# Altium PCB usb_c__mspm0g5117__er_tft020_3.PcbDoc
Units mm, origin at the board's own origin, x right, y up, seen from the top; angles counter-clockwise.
Board outline 82 x 52 mm, 2 copper layers (Top, Bottom), stack 0 mm thick; 29 components, 27 nets, 174 pads, 100 vias.
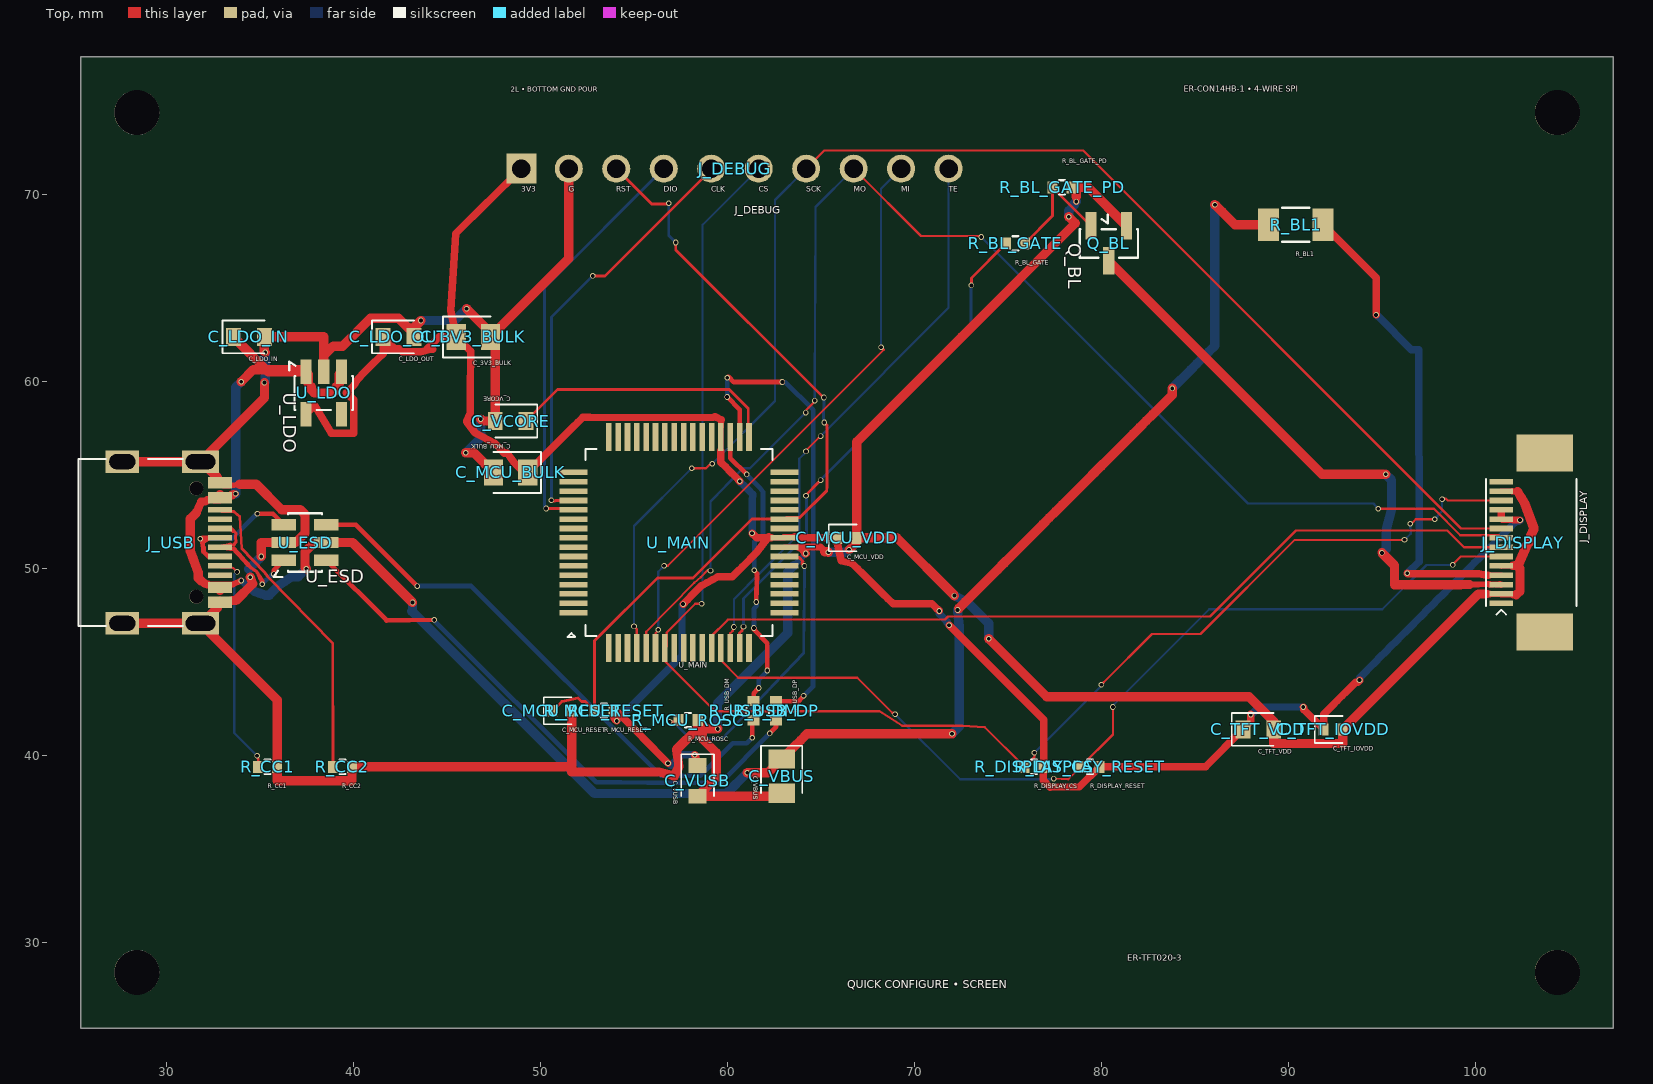
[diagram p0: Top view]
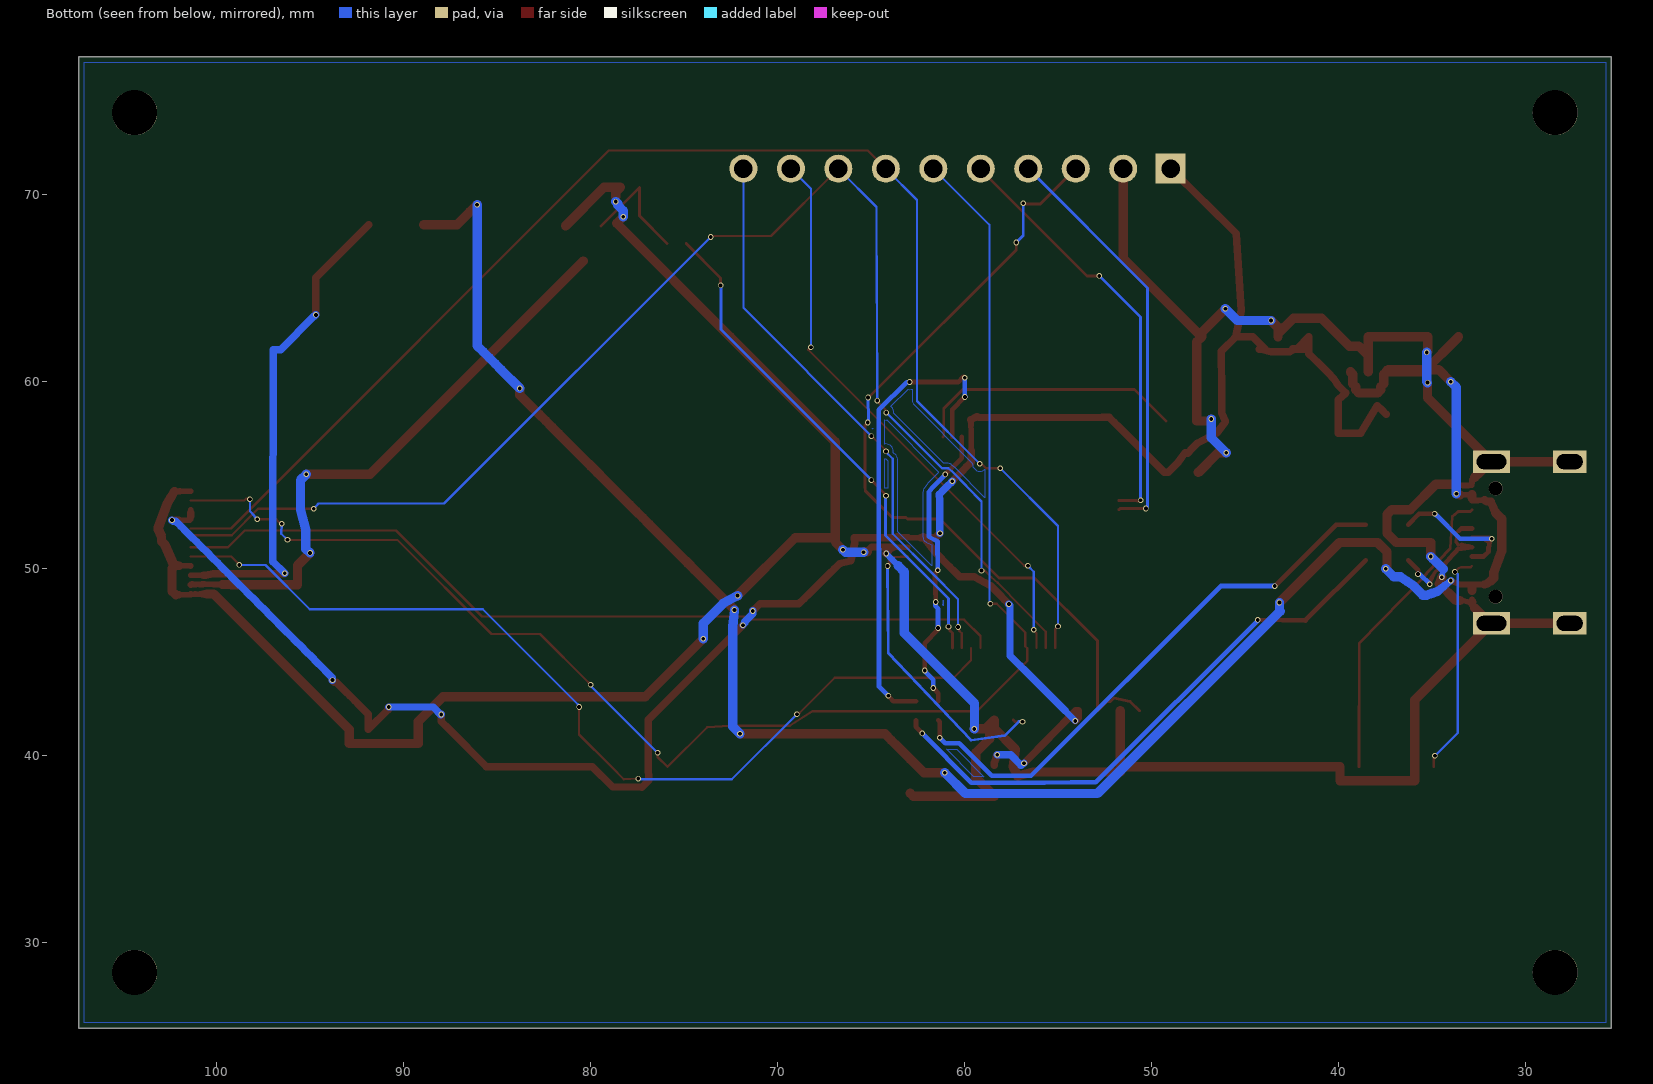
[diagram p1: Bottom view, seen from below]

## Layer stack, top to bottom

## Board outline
25.4,77.4 107.4,77.4 107.4,25.4 25.4,25.4

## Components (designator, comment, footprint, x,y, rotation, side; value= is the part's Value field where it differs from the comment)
C_3V3_BULK "" TSCIRCUIT-2.8500x1.4000mm 46.4,62.4 r0 top
C_LDO_IN "" TSCIRCUIT-2.4500x0.9500mm 34.4,62.4 r0 top
C_LDO_OUT "" TSCIRCUIT-2.4500x0.9500mm 42.4,62.4 r0 top
C_MCU_BULK "" TSCIRCUIT-2.8500x1.4000mm 48.4,55.15 r180 top
C_MCU_RESET "" TSCIRCUIT-1.5600x0.6400mm 51.15,42.4 r0 top
C_MCU_VDD "" TSCIRCUIT-1.5600x0.6400mm 66.4,51.65 r0 top
C_TFT_IOVDD "" TSCIRCUIT-1.5600x0.6400mm 92.4,41.4 r0 top
C_TFT_VDD "" TSCIRCUIT-2.4500x0.9500mm 88.4,41.4 r0 top
C_VBUS "" TSCIRCUIT-1.4000x2.8500mm 62.9,38.9 r270 top
C_VCORE "" TSCIRCUIT-2.4500x0.9500mm 48.4,57.9 r180 top
C_VUSB "" TSCIRCUIT-0.9500x2.4500mm 58.4,38.65 r270 top
J_DEBUG "" TSCIRCUIT-24.3600x1.5000mm 60.4,71.4 r0 top
J_DISPLAY "" TSCIRCUIT-4.4500x11.5800mm 103,51.4 r90 top
J_USB "" TSCIRCUIT-6.7732x9.8502mm 30.113,51.4 r90 top
Q_BL "" TSCIRCUIT-2.5000x3.3500mm 80.4,67.4 r270 top
R_BL1 "" TSCIRCUIT-4.0500x1.7500mm 90.4,68.4 r0 top
R_BL_GATE "" TSCIRCUIT-1.5600x0.6400mm 75.4,67.4 r0 top
R_BL_GATE_PD "" TSCIRCUIT-1.5600x0.6400mm 77.9,70.4 r0 top
R_CC1 "" TSCIRCUIT-1.5600x0.6400mm 35.4,39.4 r0 top
R_CC2 "" TSCIRCUIT-1.5600x0.6400mm 39.4,39.4 r0 top
R_DISPLAY_CS "" TSCIRCUIT-1.5600x0.6400mm 76.4,39.4 r0 top
R_DISPLAY_RESET "" TSCIRCUIT-1.5600x0.6400mm 79.4,39.4 r0 top
R_MCU_RESET "" TSCIRCUIT-1.5600x0.6400mm 53.4,42.4 r0 top
R_MCU_ROSC "" TSCIRCUIT-1.5600x0.6400mm 57.9,41.9 r0 top
R_USB_DM "" TSCIRCUIT-0.6400x1.5600mm 61.4,42.4 r90 top
R_USB_DP "" TSCIRCUIT-0.6400x1.5600mm 62.6,42.4 r90 top
U_ESD "" TSCIRCUIT-3.6000x2.5000mm 37.4,51.4 r0 top
U_LDO "" TSCIRCUIT-2.5000x3.6000mm 38.4,59.4 r270 top
U_MAIN "" TSCIRCUIT-12.8000x12.8000mm 57.4,51.4 r0 top

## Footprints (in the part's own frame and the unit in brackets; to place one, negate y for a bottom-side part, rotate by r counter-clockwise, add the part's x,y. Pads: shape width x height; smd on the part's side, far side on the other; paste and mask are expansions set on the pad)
TSCIRCUIT-0.6400x1.5600mm [mm]
  rect 0.54x0.64 smd: 1(-0.51,0) 2(0.51,0)
  silkscreen extent -0.15,-0.38 0.15,0.38
TSCIRCUIT-0.9500x2.4500mm [mm]
  rect 0.8x0.95 smd: 1(-0.825,0) 2(0.825,0)
  silkscreen extent -1.43,-0.87 0.82,0.87
TSCIRCUIT-1.4000x2.8500mm [mm]
  rect 1.025x1.4 smd: 1(-0.913,0) 2(0.913,0)
  silkscreen extent -1.62,-1.1 0.91,1.1
TSCIRCUIT-1.5600x0.6400mm [mm]
  rect 0.54x0.64 smd: 1(-0.51,0) 2(0.51,0)
  silkscreen extent -0.98,-0.72 0.51,0.72
TSCIRCUIT-2.4500x0.9500mm [mm]
  rect 0.8x0.95 smd: 1(-0.825,0) 2(0.825,0)
  silkscreen extent -1.43,-0.87 0.82,0.87
TSCIRCUIT-2.5000x3.3500mm [mm]
  rect 1.475x0.6 smd: 1(-0.938,-0.95) 2(-0.938,0.95) 3(0.937,0)
  silkscreen extent -1.54,-1.56 0.76,1.56
TSCIRCUIT-2.5000x3.6000mm [mm]
  rect 1.325x0.6 smd: 1(-1.137,-0.95) 2(-1.137,0) 3(-1.137,0.95) 4(1.138,0.95) 5(1.138,-0.95)
  silkscreen extent -1.69,-1.84 0.91,1.56
TSCIRCUIT-2.8500x1.4000mm [mm]
  rect 1.025x1.4 smd: 1(-0.913,0) 2(0.913,0)
  silkscreen extent -1.63,-1.1 0.91,1.1
TSCIRCUIT-3.6000x2.5000mm [mm]
  rect 1.325x0.6 smd: 1(-1.137,-0.95) 2(-1.137,0) 3(-1.137,0.95) 4(1.138,0.95) 5(1.138,0) 6(1.138,-0.95)
  silkscreen extent -1.69,-1.84 0.91,1.56
TSCIRCUIT-4.0500x1.7500mm [mm]
  rect 1.125x1.75 smd: 1(-1.462,0) 2(1.463,0)
  silkscreen extent -0.73,-0.91 0.73,0.91
TSCIRCUIT-4.4500x11.5800mm [mm]
  rect 0.3x1.25 smd: 1(-3.25,1.6) 2(-2.75,1.6) 3(-2.25,1.6) 4(-1.75,1.6) 5(-1.25,1.6) 6(-0.75,1.6) 7(-0.25,1.6) 8(0.25,1.6) 9(0.75,1.6) 10(1.25,1.6) 11(1.75,1.6) 12(2.25,1.6) 13(2.75,1.6) 14(3.25,1.6)
  rect 2x3 smd: 15(4.79,-0.725) 16(-4.79,-0.725)
  silkscreen extent -3.85,-2.43 3.4,2.42
TSCIRCUIT-6.7732x9.8502mm [mm]
  rect 0.3x1.3 smd: 1(-3.35,-2.737) 2(-3.05,-2.737) 3(-2.55,-2.737) 4(-2.25,-2.737) 5(-1.75,-2.737) 6(-1.25,-2.737) 7(-0.75,-2.737) 8(-0.25,-2.737) 9(0.25,-2.737) 10(0.75,-2.737) 11(1.25,-2.737) 12(1.75,-2.737) 13(2.55,-2.737) 14(2.25,-2.737) 15(3.35,-2.737) 16(3.05,-2.737)
  rect 1.2x2 hole 0.8 slot 1.6 at 90 deg: 17(-4.325,-1.693) 18(4.325,-1.693)
  rect 1.2x1.8 hole 0.8 slot 1.4 at 90 deg: 19(4.325,2.487) 20(-4.325,2.487)
  round 0.75 hole 0.75 unplated: NPTH-1(-2.9,-1.468) NPTH-2(2.9,-1.468)
  silkscreen extent -4.47,-0.75 4.47,4.83
TSCIRCUIT-12.8000x12.8000mm [mm]
  rect 1.5x0.3 smd: 1(-5.65,-3.75) 2(-5.65,-3.25) 3(-5.65,-2.75) 4(-5.65,-2.25) 5(-5.65,-1.75) 6(-5.65,-1.25) 7(-5.65,-0.75) 8(-5.65,-0.25) 9(-5.65,0.25) 10(-5.65,0.75) 11(-5.65,1.25) 12(-5.65,1.75) 13(-5.65,2.25) 14(-5.65,2.75) 15(-5.65,3.25) 16(-5.65,3.75) 33(5.65,3.75) 34(5.65,3.25) 35(5.65,2.75) 36(5.65,2.25) 37(5.65,1.75) 38(5.65,1.25) 39(5.65,0.75) 40(5.65,0.25) 41(5.65,-0.25) 42(5.65,-0.75) 43(5.65,-1.25) 44(5.65,-1.75) 45(5.65,-2.25) 46(5.65,-2.75) 47(5.65,-3.25) 48(5.65,-3.75)
  rect 0.3x1.5 smd: 17(-3.75,5.65) 18(-3.25,5.65) 19(-2.75,5.65) 20(-2.25,5.65) 21(-1.75,5.65) 22(-1.25,5.65) 23(-0.75,5.65) 24(-0.25,5.65) 25(0.25,5.65) 26(0.75,5.65) 27(1.25,5.65) 28(1.75,5.65) 29(2.25,5.65) 30(2.75,5.65) 31(3.25,5.65) 32(3.75,5.65) 49(3.75,-5.65) 50(3.25,-5.65) 51(2.75,-5.65) 52(2.25,-5.65) 53(1.75,-5.65) 54(1.25,-5.65) 55(0.75,-5.65) 56(0.25,-5.65) 57(-0.25,-5.65) 58(-0.75,-5.65) 59(-1.25,-5.65) 60(-1.75,-5.65) 61(-2.25,-5.65) 62(-2.75,-5.65) 63(-3.25,-5.65) 64(-3.75,-5.65)
  silkscreen extent -5.95,-5.05 5,5
TSCIRCUIT-24.3600x1.5000mm [mm]
  rect 1.6x1.6 hole 1: 1(-11.43,0)
  round 1.5 hole 1: 2(-8.89,0) 3(-6.35,0) 4(-3.81,0) 5(-1.27,0) 6(1.27,0) 7(3.81,0) 8(6.35,0) 9(8.89,0) 10(11.43,0)

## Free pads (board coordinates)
  round 2.4 hole 2.4 unplated: NPTH-3(28.4,28.4) NPTH-4(104.4,28.4) NPTH-5(28.4,74.4) NPTH-6(104.4,74.4)

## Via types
v1: diameter 0.3, hole 0.2, Top to Bottom, 100 vias

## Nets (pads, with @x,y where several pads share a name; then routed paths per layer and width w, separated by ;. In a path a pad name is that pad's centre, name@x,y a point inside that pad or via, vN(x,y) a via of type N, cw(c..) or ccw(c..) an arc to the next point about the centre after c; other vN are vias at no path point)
".J_DEBUG > .pin4 to .U_MAIN > .pin12": J_DEBUG.4 U_MAIN.12 | length 22.3
  Top w0.15: v1(50.297,53.22) 51.68,53.22 U_MAIN.12
  Bottom w0.15: v1(50.297,53.22) 50.285,53.232 50.204,53.313 50.204,53.447 50.204,65.014 J_DEBUG.4
".J_DEBUG > .pin5 to .U_MAIN > .pin13": J_DEBUG.5 U_MAIN.13 | length 22.9
  Top w0.15: v1(50.582,53.664) 50.63,53.616 50.764,53.616 50.799,53.65 U_MAIN.13 ; v1(52.787,65.664) 53.449,65.663 58.819,71.03 58.817,71.087 J_DEBUG.5
  Bottom w0.15: v1(50.582,53.664) 50.582,63.459 52.67,65.547 v1(52.787,65.664)
".U_MAIN > .pin42 to .R_MCU_ROSC > .pin1": R_MCU_ROSC.1 U_MAIN.42 | length 16.1
  Top w0.15: v1(56.896,41.815) 57.305,41.815 R_MCU_ROSC.1 ; U_MAIN.42 63.812,50.612 64.037,50.387 63.977,50.282 v1(64.117,50.142)
  Bottom w0.15: v1(56.896,41.815) 56.915,41.834 57.086,41.834 57.837,41.082 59.65,40.825 64.079,45.487 v1(64.117,50.142)
BACKLIGHT_ANODE_1: J_DISPLAY.4 R_BL1.2 | length 26.3
  Top w0.3: 100.775,49.65 100.8,49.65 100.9,49.65 101,49.65 101.1,49.65 101.2,49.65 101.3,49.65 J_DISPLAY.4
  Top w0.343: 100.7,49.65 100.775,49.65
  Top w0.4: R_BL1.2 94.701,65.562 v1(94.701,63.576) ; v1(96.371,49.758) 96.395,49.732 96.438,49.719 100.188,49.726 100.6,49.65 100.7,49.65
  Bottom w0.4: v1(94.701,63.576) 94.783,63.494 94.804,63.494 96.585,61.714 96.984,61.714 96.998,50.367 v1(96.371,49.758)
BACKLIGHT_CATHODE: J_DISPLAY.3 Q_BL.3 | length 31.7
  Top w0.303: J_DISPLAY.3@100.932,49.158 101.026,49.158 J_DISPLAY.3@101.12,49.159
  Top w0.309: J_DISPLAY.3@101.12,49.159 J_DISPLAY.3@101.214,49.16
  Top w0.311: J_DISPLAY.3@100.839,49.159 J_DISPLAY.3@100.932,49.158 ; J_DISPLAY.3@101.214,49.16 J_DISPLAY.3@101.307,49.163
  Top w0.325: 99.697,49.15 100.174,49.161 100.651,49.171 100.745,49.157
  Top w0.33: J_DISPLAY.3@100.776,49.157 J_DISPLAY.3@100.839,49.159
  Top w0.35: 100.745,49.157 100.775,49.157
  Top w0.352: J_DISPLAY.3@101.307,49.163 J_DISPLAY.3
  Top w0.5: Q_BL.3 87.313,59.549 91.807,55.055 v1(95.21,55.055) ; v1(95.012,50.843) 95.684,50.171 95.684,49.807 95.684,49.14 99.22,49.14 99.697,49.15
  Bottom w0.5: v1(95.012,50.843) 95.234,51.053 95.234,51.547 95.235,52.041 95.525,53.15 95.525,54.74 v1(95.21,55.055)
BACKLIGHT_GATE: Q_BL.1 R_BL_GATE.2 R_BL_GATE_PD.1 | length 6.5
  Top w0.15: R_BL_GATE.2 77.39,68.88 R_BL_GATE_PD.1 79.45,68.34 Q_BL.1
BACKLIGHT_PWM: R_BL_GATE.1 U_MAIN.50 | length 27.6
  Top w0.15: U_MAIN.50 60.65,46.552 60.79,46.692 60.79,46.839 v1(60.859,46.903) ; v1(64.199,53.908) 64.231,53.978 64.886,54.633 64.886,54.65 v1(64.98,54.738) ; v1(73.049,65.154) 73.049,65.559 R_BL_GATE.1
  Bottom w0.15: v1(60.859,46.903) 60.854,48.403 63.16,50.709 64.227,51.776 64.227,53.763 64.227,53.904 v1(64.199,53.908) ; v1(64.98,54.738) 73.036,62.8 73.036,65.141 v1(73.049,65.154)
DISPLAY_CS_N: J_DEBUG.6 J_DISPLAY.12 R_DISPLAY_CS.1 U_MAIN.58 | length 82.5
  Top w0.12: v1(58.613,48.124) 58.281,48.124 56.749,46.592 56.749,45.849 U_MAIN.58 56.65,45.059 59.332,42.377 68.123,42.377 69.337,41.599 69.696,41.599 72.57,41.591 73.767,41.523 R_DISPLAY_CS.1 76.419,39.929 v1(76.419,40.146) ; v1(80.004,43.795) 80.13,43.921 80.133,43.921 82.713,46.501 85.31,46.501 90.35,51.541 v1(96.218,51.541) ; v1(96.53,52.405) 96.617,52.47 96.657,52.47 96.828,52.64 v1(97.835,52.64) ; v1(98.229,53.72) 98.255,53.746 98.44,53.746 98.536,53.65 J_DISPLAY.12
  Bottom w0.12: v1(58.613,48.124) 58.67,48.181 58.67,48.214 58.67,68.4 J_DEBUG.6 ; v1(76.419,40.146) 76.437,40.164 80.004,43.731 v1(80.004,43.795) ; v1(96.218,51.541) 96.224,51.547 96.552,51.875 v1(96.53,52.405) ; v1(97.835,52.64) 97.98,52.785 97.98,52.824 98.229,53.073 v1(98.229,53.72)
DISPLAY_DC: J_DISPLAY.7 U_MAIN.53 | length 45.6
  Top w0.12: U_MAIN.53 59.15,46.398 59.929,47.177 60.033,47.282 71.635,47.282 71.796,47.443 85.817,47.443 90.412,52.039 98.512,52.039 99.401,51.15 J_DISPLAY.7
DISPLAY_MISO: J_DEBUG.9 U_MAIN.59 | length 31.3
  Top w0.12: U_MAIN.59 56.15,46.541 56.298,46.689 56.298,46.736 v1(56.296,46.738) ; v1(56.608,50.153) 56.801,50.153 68.363,61.715 68.351,61.715 v1(68.216,61.85)
  Bottom w0.12: v1(56.296,46.738) 56.296,49.841 56.575,50.12 v1(56.608,50.153) ; v1(68.216,61.85) 68.216,70.326 J_DEBUG.9
DISPLAY_MOSI: J_DEBUG.8 J_DISPLAY.8 U_MAIN.60 | length 73.4
  Top w0.12: U_MAIN.60 55.65,46.629 58.217,49.242 58.564,49.543 58.918,49.897 v1(59.091,49.897) ; v1(64.181,58.352) 64.196,58.478 64.64,58.922 64.64,58.941 v1(64.672,58.994) ; J_DEBUG.8 70.352,67.798 73.508,67.798 73.53,67.798 v1(73.581,67.747) ; v1(94.815,53.201) 97.793,53.201 99.208,51.786 101.264,51.786 J_DISPLAY.8
  Bottom w0.12: v1(59.091,49.897) 59.091,53.594 60.654,55.195 60.867,55.37 61.208,55.37 v1@64.148,58.31 ; v1@64.148,58.31 v1(64.181,58.352) ; v1(64.672,58.994) 64.703,69.353 J_DEBUG.8 ; v1(73.581,67.747) 87.841,53.487 94.552,53.487 94.556,53.487 v1(94.815,53.201)
DISPLAY_RESET_N: J_DISPLAY.6 R_DISPLAY_RESET.1 U_MAIN.52 | length 50.9
  Top w0.12: U_MAIN.52 59.65,45.094 60.582,44.162 66.945,44.162 68.809,42.298 68.887,42.298 v1(68.968,42.217) ; v1(77.453,38.771) 78.225,38.735 R_DISPLAY_RESET.1 80.62,41.13 v1(80.62,42.602) ; v1(98.8,50.2) 98.818,50.218 98.818,50.244 99.225,50.65 J_DISPLAY.6
  Bottom w0.12: v1(68.968,42.217) 72.449,38.736 77.421,38.736 v1(77.453,38.771) ; v1(80.62,42.602) 80.692,42.7 80.692,42.743 85.779,47.831 95.032,47.831 97.402,50.2 v1(98.8,50.2)
DISPLAY_SCLK: J_DEBUG.7 J_DISPLAY.9 U_MAIN.61 | length 76
  Top w0.12: v1(55.001,46.91) 55.15,46.761 55.15,46.75 U_MAIN.61 ; v1(58.093,55.379) 58.848,55.379 59.02,55.551 59.113,55.551 v1(59.179,55.617) ; J_DEBUG.7 65.189,72.379 79.017,72.379 99.246,52.15 J_DISPLAY.9
  Bottom w0.12: v1(55.001,46.91) 55.001,52.287 58.091,55.377 v1(58.093,55.379) ; v1(59.179,55.617) 62.537,58.975 62.537,69.721 62.537,69.727 J_DEBUG.7
DISPLAY_TE: J_DEBUG.10 U_MAIN.51 | length 30.5
  Top w0.12: U_MAIN.51 60.15,46.55 60.291,46.691 60.291,46.821 v1(60.345,46.88) ; v1(64.201,56.272) 64.242,56.366 64.881,57.005 64.881,57.015 v1(64.982,57.092)
  Bottom w0.12: v1(60.345,46.88) 60.35,48.37 61.77,49.791 63.845,51.865 63.845,55.678 63.845,55.875 64.235,56.265 v1(64.201,56.272) ; v1(64.982,57.092) 71.83,63.964 J_DEBUG.10
GND: C_3V3_BULK.2 C_LDO_IN.2 C_LDO_OUT.2 C_MCU_BULK.2 C_MCU_RESET.2 C_MCU_VDD.2 C_TFT_IOVDD.2 C_TFT_VDD.2 C_VBUS.2 C_VCORE.2 C_VUSB.2 J_DEBUG.2 J_DISPLAY.2 J_DISPLAY.5 J_DISPLAY.13 J_USB.1 J_USB.2 J_USB.15 J_USB.16 J_USB.17 J_USB.18 J_USB.19 J_USB.20 Q_BL.2 R_BL_GATE_PD.2 R_CC1.2 R_CC2.2 R_MCU_ROSC.2 U_ESD.2 U_LDO.2 U_MAIN.41 | length 222.5
  Top w0.275: J_USB.1@32.849,48.2 J_USB.2
  Top w0.288: J_USB.15@32.849,54.6 J_USB.16 J_USB.16@32.945,54.461
  Top w0.3: J_USB.1@32.699,47.9 J_USB.1 J_USB.2@32.849,48.2 ; 32.699,54.9 J_USB.15 J_USB.16@32.849,54.6 ; J_USB.2 33,48.2 33.4,48.3 33.499,48.3 ; J_DISPLAY.2 101.4,48.6 101.8,48.6 J_DISPLAY.2@102.025,48.6 ; J_DISPLAY.5 J_DISPLAY.5@101.765,50.155 ; J_DISPLAY.13 101.702,54.15 J_DISPLAY.13@101.989,54.142 ; U_MAIN.41@63.144,51.15 U_MAIN.41 U_MAIN.41@63.144,51.15 ; U_MAIN.41@63.144,51.15 U_MAIN.41@63.238,51.15 ; U_MAIN.41@63.144,51.15 U_MAIN.41@63.238,51.15 ; U_MAIN.41@63.238,51.15 U_MAIN.41@63.331,51.15 ; U_MAIN.41@63.238,51.15 U_MAIN.41@63.331,51.15 ; U_MAIN.41@63.331,51.15 U_MAIN.41@63.425,51.15 ; U_MAIN.41@63.331,51.15 U_MAIN.41@63.425,51.15 ; U_MAIN.41@63.425,51.15 U_MAIN.41@63.519,51.15 ; U_MAIN.41@63.425,51.15 U_MAIN.41@63.519,51.15 ; U_MAIN.41@63.519,51.15 U_MAIN.41@63.612,51.15 ; U_MAIN.41@63.519,51.15 U_MAIN.41@63.612,51.15 ; U_MAIN.41@63.612,51.15 U_MAIN.41@63.706,51.15 ; U_MAIN.41@63.612,51.15 U_MAIN.41@63.706,51.15 ; U_MAIN.41@63.706,51.15 63.8,51.15 U_MAIN.41@63.706,51.15
  Top w0.301: J_DISPLAY.2@100.899,48.638 101.024,48.638 J_DISPLAY.2@101.149,48.639
  Top w0.308: J_DISPLAY.2@101.149,48.639 101.275,48.638 J_DISPLAY.2
  Top w0.312: J_USB.16@32.945,54.461 33.037,54.45 33.316,54.457 33.596,54.465 33.9,54.525
  Top w0.316: J_DISPLAY.5 101.801,50.155 J_DISPLAY.5@102.025,50.158
  Top w0.318: J_DISPLAY.5@101.765,50.155 102.129,50.16
  Top w0.324: 100.775,48.636 J_DISPLAY.2@100.899,48.638
  Top w0.334: J_DISPLAY.13@101.989,54.142 102.275,54.134
  Top w0.35: v1(78.658,69.64) 78.658,69.896 ; 100.774,48.636 100.775,48.636
  Top w0.375: U_MAIN.41@63.8,51.15 64.189,51.15 64.577,51.15 64.966,51.15 65.202,50.914 ; 100.648,48.637 100.774,48.636
  Top w0.4: U_MAIN.41@63.8,51.15 64.056,51.025 ; 102.025,48.6 102.2,48.6
  Top w0.433: 100.524,48.647 100.648,48.637
  Top w0.45: 64.056,51.025 64.17,50.83 v1(64.182,50.812)
  Top w0.475: v1(66.507,51.014) 66.91,51.417 C_MCU_VDD.2 ; 102.025,50.158 102.202,50.16 ; 102.129,50.16 102.2,50.2 102.4,50 102.4,49.6 ; 102.2,48.6 102.4,48.8 ; 102.275,54.134 102.456,53.826
  Top w0.5: J_USB.20 J_USB.17 ; J_USB.19 J_USB.18 ; J_USB.1@32.699,47.9 32.474,47.675 31.874,47.075 J_USB.17 ; 32.699,54.9 32.474,55.125 31.874,55.725 J_USB.18 ; 33.499,48.3 33.7,48.3 34.6,49.2 v1(34.469,49.537) ; 33.9,54.525 34.775,54.525 36.15,53.15 37.15,53.15 37.4,52.9 37.4,51.9 36.9,51.4 U_ESD.2 35.057,51.4 v1(35.057,50.65) ; v1(35.227,59.956) 35.227,59.146 J_USB.18 ; v1(35.268,61.571) 35.225,61.615 C_LDO_IN.2 38.4,62.4 U_LDO.2 38.4,61.4 38.9,61.9 39.4,61.9 40.9,63.4 42.4,63.4 43.225,62.575 C_LDO_OUT.2 43.225,62.9 43.578,63.253 v1(43.6,63.275) ; v1(46,56.2) 46.437,56.2 C_MCU_BULK.2 ; v1(46.042,63.91) 47.313,62.64 C_3V3_BULK.2 ; v1(46.805,58.005) 46.911,57.9 C_VCORE.2 47.575,62.138 C_3V3_BULK.2 ; J_DEBUG.2 51.51,66.597 C_3V3_BULK.2 ; v1(59.483,41.429) 59.182,41.429 58.881,41.429 58.646,41.664 R_MCU_ROSC.2 ; C_VBUS.2 62.737,37.825 C_VUSB.2 59.4,38.825 59.4,40.15 58.65,40.9 58.65,41.65 58.41,41.89 R_MCU_ROSC.2 ; 65.202,50.914 65.361,50.914 v1(65.399,50.876) ; v1(72.141,48.56) 69.051,51.65 C_MCU_VDD.2 66.91,52.137 66.91,52.623 66.91,53.11 66.91,53.596 66.91,54.083 66.91,54.569 66.91,55.056 66.91,55.543 66.91,56.782 72.529,62.401 78.605,68.476 v1(78.251,68.83) ; v1(73.977,46.249) 77.076,43.15 80.9,43.15 87.9,43.15 88.4,42.65 89.225,41.825 C_TFT_VDD.2 89.225,40.65 92.91,40.65 C_TFT_IOVDD.2 100.16,48.64 100.4,48.645 100.524,48.647 ; 78.658,69.896 78.658,70.152 R_BL_GATE_PD.2 79.287,70.4 Q_BL.2 ; 102.202,50.16 102.4,50.358 102.4,50.4 102.588,50.838 102.775,51.275 102.962,51.463 102.962,51.713 103.15,52.15 102.638,53.517 102.456,53.826 ; 102.4,48.8 102.4,49.2 102.4,49.6 ; J_USB.17 35.91,42.971 R_CC1.2 35.91,38.65 39.91,38.65 R_CC2.2 40.391,39.4 40.871,39.4 41.352,39.4 41.832,39.4 42.313,39.4 42.793,39.4 43.274,39.4 43.754,39.4 44.235,39.4 44.715,39.4 45.196,39.4 45.676,39.4 51.66,39.4 C_MCU_RESET.2 51.66,39.119 56.349,39.119 57.15,38.9 57.4,39.4 57.273,40.33 58.41,41.467 R_MCU_ROSC.2
  Bottom w0.3: 34.39,49.983 v1(34.469,49.537)
  Bottom w0.325: 63.547,50.158 63.864,50.485 v1(64.182,50.812)
  Bottom w0.5: 34.39,49.983 34.668,50.261 34.946,50.539 v1(35.057,50.65) ; v1(35.227,59.956) 35.268,59.997 v1(35.268,61.571) ; v1(43.6,63.275) 45.407,63.275 v1(46.042,63.91) ; v1(46,56.2) 46.805,57.005 v1(46.805,58.005) ; v1(59.483,41.429) 59.468,41.444 59.468,41.644 59.468,42.029 59.468,42.414 59.468,42.798 63.23,46.56 63.23,49.831 63.547,50.158 ; v1(65.399,50.876) 66.369,50.876 v1(66.507,51.014) ; v1(72.141,48.56) 72.9,48.15 73.977,47.073 v1(73.977,46.249) ; v1(78.251,68.83) 78.251,69.148 78.556,69.453 78.556,69.538 v1(78.658,69.64)
MAIN_RESET: C_MCU_RESET.1 J_DEBUG.3 R_MCU_RESET.1 U_MAIN.38 | length 44.8
  Top w0.15: C_MCU_RESET.1 51.137,42.897 52,43.075 52.184,42.897 52.393,42.897 R_MCU_RESET.1 52.89,46.145 56.252,49.507 58.161,49.507 59.816,51.162 61.304,52.65 U_MAIN.38 63.13,52.73 63.869,52.73 65.308,54.169 65.32,54.382 65.322,57.685 v1(65.173,57.82) ; J_DEBUG.3 55.948,69.502 56.764,69.502 56.816,69.502 v1(56.853,69.545) ; v1(57.233,67.451) 57.233,67.043 65.073,59.203 v1(65.16,59.157)
  Bottom w0.15: v1(56.853,69.545) 56.856,67.828 v1(57.233,67.451) ; v1(65.16,59.157) 65.129,57.971 65.179,57.921 65.179,57.826 v1(65.173,57.82)
MSP_VCORE: C_VCORE.1 U_MAIN.32 | length 14.5
  Top w0.15: C_VCORE.1 50.903,59.578 60.03,59.578 60.094,59.578 61.109,58.563 61.109,57.091 U_MAIN.32
usb-dm-mcu: R_USB_DM.2 U_MAIN.30 | length 15.9
  Top w0.25: U_MAIN.30 60.15,55.91 v1(61.026,55.042) ; R_USB_DM.2 61.4,43.335 61.63,43.565 61.63,43.573 v1(61.675,43.618) ; v1(61.414,46.828) 61.401,46.815 61.401,46.748 62.132,46.017 v1(62.132,44.553) ; v1(61.429,49.918) 61.433,49.914 61.433,49.902 61.579,49.756 v1(61.538,48.216)
  Bottom w0.25: v1(61.026,55.042) 61.077,54.983 61.733,54.327 61.9,54.1 61.9,51.7 61.443,51.47 v1(61.429,49.918) ; v1(61.414,46.828) 61.414,47.862 61.555,48.013 61.559,48.202 v1(61.538,48.216) ; v1(61.675,43.618) 61.675,44.063 62.067,44.455 62.067,44.488 v1(62.132,44.553)
usb-dm-phy: R_USB_DM.1 U_ESD.4 | length 30.2
  Top w0.25: U_ESD.4 40.122,52.35 43.244,49.228 ; 43.245,49.228 v1(43.403,49.07) ; v1(61.322,40.955) 61.322,41.812 R_USB_DM.1
  Bottom w0.25: v1(43.403,49.07) 46.283,49.07 56.443,38.917 58.538,38.917 60.281,40.653 61.029,40.653 61.31,40.934 61.31,40.943 v1(61.322,40.955)
usb-dm-port: J_USB.7 J_USB.9 U_ESD.3 | length 8.8
  Top w0.25: v1(31.799,51.6) 31.809,51.61 31.866,51.61 31.906,51.65 J_USB.9 32.275,51.65 31.9,51.4 31.963,51.131 31.963,50.925 31.962,50.9 32.238,50.65 32.442,50.65 32.645,50.65 J_USB.7 ; v1(34.85,52.94) 35.685,52.928 U_ESD.3
  Bottom w0.25: v1(31.799,51.6) 33.493,51.6 34.769,52.876 34.786,52.876 v1(34.85,52.94)
usb-dp-mcu: R_USB_DP.2 U_MAIN.31 | length 25.9
  Top w0.25: v1(59.977,59.187) 60.65,58.514 U_MAIN.31 ; v1(59.992,60.219) 60.029,60.256 60.056,60.256 60.327,59.985 v1(62.94,59.985) ; R_USB_DP.2 63.802,42.91 64.013,43.121 64.013,43.145 v1(64.072,43.204)
  Bottom w0.25: v1(59.977,59.187) 59.966,59.198 59.966,59.234 59.992,59.26 v1(59.992,60.219) ; v1(62.94,59.985) 62.954,59.971 63.095,59.971 64.593,58.503 64.579,43.7 v1(64.072,43.204)
usb-dp-phy: R_USB_DP.1 U_ESD.6 | length 30.6
  Top w0.25: U_ESD.6 41.759,47.229 v1(44.309,47.259) ; v1(62.257,41.186) 62.316,41.245 62.316,41.258 62.6,41.541 R_USB_DP.1
  Bottom w0.25: v1(44.309,47.259) 44.317,47.225 52.975,38.585 55.711,38.551 59.63,38.552 v1(62.257,41.186)
usb-dp-port: J_USB.8 J_USB.10 U_ESD.1 | length 7.5
  Top w0.156: J_USB.8@33.387,51.28 33.604,51.257 33.651,51.405 33.7,51.4
  Top w0.162: 33.542,52.032 33.7,51.9 33.684,51.711 33.7,51.4
  Top w0.188: 34.5,50.05 34.65,49.95 34.8,49.85 34.9,49.683
  Top w0.2: 34.35,50.217 34.5,50.05 ; 34.9,49.683 35,49.517
  Top w0.238: J_USB.8@33.028,51.193 33.207,51.237 J_USB.8@33.387,51.28
  Top w0.25: J_USB.10 33.037,52.15 33.225,52.15 33.414,52.15 33.542,52.032 ; J_USB.8@33.028,51.193 J_USB.8 33.037,51.125 33.225,51.1 33.412,51.075 33.6,51.05 33.75,50.883 33.9,50.717 34.05,50.55 34.2,50.383 34.35,50.217 ; 35,49.517 35.1,49.35 v1(35.116,49.171) ; v1(35.739,49.712) 35.729,49.916 35.862,50.05 35.996,50.183 36.129,50.317 U_ESD.1
  Bottom w0.25: v1(35.116,49.171) 35.116,49.191 35.282,49.357 35.447,49.522 35.613,49.688 35.715,49.688 v1(35.739,49.712)
USB_CC1: J_USB.6 R_CC1.1 | length 12.1
  Top w0.12: J_USB.6 32.917,50.082 33.416,50.082 33.435,50.082 33.578,50.017 v1(33.763,49.826) ; v1(34.835,39.986) 34.841,39.98 34.841,39.88 34.89,39.831 R_CC1.1
  Bottom w0.12: v1(33.763,49.826) 33.608,49.705 33.608,49.613 33.608,41.213 v1(34.835,39.986)
USB_CC2: J_USB.12 R_CC2.1 | length 16.5
  Top w0.15: J_USB.12 32.934,53.065 33.562,53.065 33.904,52.794 34.015,51.087 35.219,49.823 35.398,49.577 38.887,45.997 R_CC2.1
VBUS5: C_LDO_IN.1 C_VBUS.1 J_USB.3 J_USB.4 J_USB.13 J_USB.14 R_BL1.1 U_ESD.5 U_LDO.1 U_LDO.3 | length 112.3
  Top w0.3: 32.181,53.666 32.548,53.65 J_USB.14 32.849,53.8 ; J_USB.4@32.199,49.154 32.519,49.154 32.845,49.154 J_USB.4 J_USB.3@32.849,49 ; J_USB.13 32.943,53.95 33.037,53.95 33.13,53.95 33.224,53.95 33.318,53.95 33.412,53.95 33.499,53.95
  Top w0.32: J_USB.4 J_USB.4@33.192,49.155
  Top w0.325: J_USB.4@33.192,49.155 33.535,49.16 v1(33.985,49.362)
  Top w0.35: v1@33.573,54.012 33.658,54.012 v1(33.684,54.012) ; v1(72.309,47.786) v1@72.377,47.854
  Top w0.375: 33.505,53.95 33.511,53.95 v1@33.573,54.012
  Top w0.437: 31.713,53.289 31.838,53.588 32.056,53.588 32.181,53.666
  Top w0.45: 31.588,52.991 31.713,53.289 ; 31.838,49.358 32.025,49.212 32.193,49.154 J_USB.4@32.199,49.154
  Top w0.475: 33.499,53.95 33.505,53.95
  Top w0.5: 31.588,52.991 31.258,52.662 31.258,52.233 31.258,51.804 31.258,51.375 31.258,50.947 31.403,50.55 31.548,50.152 31.693,49.755 31.693,49.503 31.838,49.358 ; J_USB.3 J_USB.4@32.849,49 ; J_USB.13@32.849,53.8 J_USB.13 ; C_LDO_IN.1 35.438,60.537 U_LDO.1 ; v1(33.988,60.007) 34.631,60.65 35.4,60.65 37.337,60.65 U_LDO.1 ; v1(37.458,49.99) 37.4,50.048 37.4,50.9 37.9,51.4 U_ESD.5 39.94,51.4 v1(43.152,48.188) ; U_LDO.3 39.35,60.517 39.233,60.4 39.233,59.9 39.067,59.733 39.067,59.567 38.9,59.4 37.9,59.4 37.733,59.567 37.733,59.733 37.567,59.9 37.567,60.4 37.4,60.567 37.421,60.567 U_LDO.1 ; v1(61.051,39.08) 62.168,39.08 C_VBUS.1 63.238,40.15 63.576,40.488 63.914,40.826 64.251,41.164 64.736,41.164 65.221,41.164 65.706,41.164 66.191,41.164 66.676,41.164 67.161,41.164 67.646,41.164 68.131,41.164 68.616,41.164 69.101,41.164 69.586,41.164 70.071,41.164 70.556,41.164 71.041,41.164 71.526,41.164 v1(72.011,41.164) ; v1@72.377,47.854 72.377,47.876 72.723,48.222 73.069,48.568 73.415,48.914 73.761,49.26 74.107,49.606 74.453,49.951 74.798,50.297 75.144,50.643 75.49,50.989 75.836,51.335 76.182,51.681 76.528,52.027 76.874,52.373 77.22,52.719 77.566,53.065 77.912,53.411 78.258,53.757 78.604,54.103 78.95,54.449 79.296,54.795 79.642,55.141 79.988,55.487 80.334,55.833 80.68,56.178 81.025,56.524 81.371,56.87 81.717,57.216 82.063,57.562 82.409,57.908 82.755,58.254 83.101,58.6 83.447,58.946 83.793,59.292 v1(83.793,59.645) ; v1(86.076,69.473) 86.113,69.436 86.117,69.436 86.462,69.091 86.807,68.745 87.153,68.4 87.599,68.4 88.045,68.4 88.491,68.4 R_BL1.1
  Bottom w0.375: v1(33.985,49.362) 34.349,49.069
  Bottom w0.45: 34.349,49.069 34.713,48.775
  Bottom w0.5: v1(33.684,54.012) 33.684,59.703 v1(33.988,60.007) ; 34.713,48.775 34.994,48.681 35.275,48.587 35.484,48.587 35.977,49.081 36.328,49.327 36.679,49.574 37.042,49.574 v1(37.458,49.99) ; v1(43.152,48.188) 43.152,47.773 43.108,47.729 52.892,37.975 59.946,37.975 v1(61.051,39.08) ; v1(72.011,41.164) 72.4,41.553 72.4,46.9 v1(72.309,47.786) ; v1(83.793,59.645) 83.811,59.663 84.135,59.987 84.458,60.31 84.782,60.634 85.105,60.957 85.429,61.281 85.752,61.604 86.076,61.928 86.076,62.4 86.076,62.871 86.076,63.343 86.076,63.814 86.076,64.286 86.076,64.757 86.076,65.229 86.076,65.701 86.076,66.172 86.076,66.644 86.076,67.115 86.076,67.587 86.076,68.058 86.076,68.53 86.076,69.001 v1(86.076,69.473)
VCC_3V3: C_3V3_BULK.1 C_LDO_OUT.1 C_MCU_BULK.1 C_MCU_VDD.1 C_TFT_IOVDD.1 C_TFT_VDD.1 C_VUSB.1 J_DEBUG.1 J_DISPLAY.10 J_DISPLAY.11 R_DISPLAY_CS.2 R_DISPLAY_RESET.2 R_MCU_RESET.2 U_LDO.5 U_MAIN.29 U_MAIN.40 | length 135
  Top w0.3: U_MAIN.29@59.65,56.3 59.65,56.373 59.65,56.711 U_MAIN.29 59.65,57.377 U_MAIN.29@59.656,57.67 ; U_MAIN.40@62.313,51.65 62.681,51.65 U_MAIN.40 ; U_MAIN.40@62.343,51.65 62.696,51.65 U_MAIN.40 ; U_MAIN.40@63.6,51.7 63,51.7 U_MAIN.40 ; 101.4,52.8 J_DISPLAY.10 101.45,52.6 101.767,52.6 J_DISPLAY.10@102.025,52.6 ; J_DISPLAY.11@101.4,53 J_DISPLAY.11
  Top w0.332: U_MAIN.29@59.656,57.67 59.662,57.963
  Top w0.375: 53.031,58.089 53.421,58.089 53.81,58.089 54.2,58.089 54.589,58.089 54.979,58.089 55.368,58.089 55.758,58.089 56.148,58.089 56.537,58.089 56.927,58.089 57.316,58.089 57.706,58.089 58.095,58.089 58.485,58.089 58.874,58.089 59.264,58.089 59.313,58.138
  Top w0.387: 52.642,58.089 53.031,58.089 ; 102.025,52.6 102.083,52.6 v1(102.4,52.6)
  Top w0.4: U_LDO.5 37.679,58.491 37.908,58.72 38.8,57.25 40,57.25 40,59.05 39.6,59.4 40,59.8 40.263,60.194 40.525,60.457 40.788,60.719 41.05,60.982 41.313,61.244 41.575,61.507 41.575,61.804 41.575,62.102 C_LDO_OUT.1 41.787,62.188 41.998,61.977 42.21,61.765 42.45,61.765 41.946,61.755 41.575,61.75 41.953,61.75 42.331,61.75 42.6,61.6 43.6,61.6 44.221,61.75 43.939,61.765 44.151,61.977 44.362,62.188 44.574,62.4 44.878,62.4 45.183,62.4 C_3V3_BULK.1 ; J_DEBUG.1 45.45,67.918 45.195,63.817 C_3V3_BULK.1 ; 52.642,58.089 52.252,58.089 51.985,57.822 51.718,57.555 51.45,57.288 51.183,57.02 50.916,56.753 50.649,56.486 50.381,56.219 50.114,55.952 49.847,55.684 49.58,55.417 C_MCU_BULK.1 49.111,55.148 48.85,55.407 48.59,55.666 48.2,56.2 48.068,56.184 47.807,56.443 47.547,56.701 46.505,57.259 46.048,57.864 46.244,58.359 46.245,58.723 46.247,59.087 46.248,59.451 46.249,59.814 46.25,60.178 46.251,60.542 46.253,60.905 46.254,61.269 46.255,61.633 45.999,61.889 45.743,62.144 C_3V3_BULK.1 ; v1(54.077,41.854) 54.001,41.93 54.001,41.938 53.91,42.029 R_MCU_RESET.2 54.053,42.4 v1(56.818,39.587) ; v1(57.624,48.105) 57.868,48.349 58.113,48.594 58.357,48.838 58.602,49.083 58.895,49.246 59.188,49.409 59.482,49.572 59.873,49.572 60.264,49.572 60.524,49.831 60.784,50.091 61.044,50.351 61.304,50.611 61.563,50.871 62.2,51.7 U_MAIN.40@62.343,51.65 ; v1(58.247,40.052) 58.4,39.625 C_VUSB.1 ; 59.313,58.138 59.662,57.963 ; 59.65,56.3 59.65,56.035 59.65,55.696 59.903,55.441 60.156,55.186 60.409,54.931 v1(60.662,54.676) ; v1(61.313,51.893) 61.361,51.845 61.381,51.845 61.576,51.65 61.944,51.65 U_MAIN.40@62.313,51.65 ; U_MAIN.40@63.6,51.7 63.85,51.65 C_MCU_VDD.1 65.88,51.366 66.085,50.415 66.685,50.276 66.956,50.008 67.228,49.739 67.5,49.471 67.772,49.202 68.043,48.934 68.315,48.665 68.587,48.397 68.858,48.128 69.203,48.129 69.547,48.129 69.891,48.129 70.235,48.13 70.579,48.13 70.924,48.131 71.078,47.976 71.233,47.822 71.246,47.822 v1(71.33,47.738) ; v1(71.856,46.976) 72.137,46.695 72.418,46.414 72.698,46.134 72.979,45.853 73.26,45.572 73.541,45.291 73.821,45.011 74.102,44.73 74.383,44.449 74.664,44.168 74.945,43.887 75.225,43.607 75.506,43.326 75.787,43.045 76.068,42.764 76.348,42.484 76.629,42.203 76.91,41.922 76.91,41.562 76.91,41.201 76.91,40.841 76.91,40.481 76.91,40.121 76.91,39.76 R_DISPLAY_CS.2 76.898,38.68 77.262,38.296 78.83,38.32 R_DISPLAY_RESET.2 85.575,39.4 C_TFT_VDD.1 88,41.825 v1(88,42.2) ; v1(90.8,42.6) 90.839,42.561 90.839,42.465 91.89,41.414 C_TFT_IOVDD.1 91.89,41.669 91.89,41.937 91.89,42.206 92.137,42.453 92.384,42.7 92.631,42.947 92.877,43.194 93.124,43.44 93.371,43.687 93.618,43.934 93.709,43.934 v1(93.815,44.04) ; 101.4,52.8 101.4,53
  Bottom w0.35: v1(54.077,41.854) 54.345,42.122 54.614,42.391
  Bottom w0.363: 71.751,47.164 71.751,47.081 v1(71.856,46.976)
  Bottom w0.4: 54.614,42.391 54.882,42.659 55.151,42.928 55.419,43.196 55.688,43.465 55.956,43.733 56.225,44.002 56.493,44.27 56.762,44.539 57.03,44.807 57.299,45.076 57.567,45.344 57.567,45.71 57.567,46.076 57.567,46.443 57.567,46.809 57.567,47.175 57.567,47.541 57.567,47.907 57.567,48.048 v1(57.624,48.105) ; v1(56.818,39.587) 56.959,39.494 56.98,39.494 57.537,40.052 v1(58.247,40.052) ; v1(60.662,54.676) 60.721,54.625 60.721,54.609 60.928,54.403 61.134,54.196 61.34,53.99 61.336,53.641 61.331,53.291 61.327,52.941 61.322,52.592 61.318,52.242 v1(61.313,51.893) ; v1(71.33,47.738) 71.33,47.584 71.54,47.374 71.751,47.164 ; v1(88,42.2) 88.014,42.186 88.429,42.6 v1(90.8,42.6) ; v1(93.815,44.04) 93.815,44.162 94.094,44.442 94.374,44.721 94.653,45.001 94.933,45.28 95.212,45.56 95.492,45.839 95.771,46.118 96.051,46.398 96.33,46.677 96.61,46.957 96.889,47.236 97.168,47.516 97.448,47.795 97.727,48.075 98.007,48.354 98.286,48.634 98.566,48.913 98.845,49.192 99.125,49.472 99.404,49.751 99.684,50.031 99.963,50.31 100.242,50.59 100.522,50.869 100.801,51.149 101.081,51.428 101.36,51.708 101.64,51.987 101.919,52.266 102.199,52.546 102.346,52.546 v1(102.4,52.6)
pads on no net: J_DISPLAY.1 J_DISPLAY.14 J_DISPLAY.15 J_DISPLAY.16 J_USB.5 J_USB.11 J_USB.NPTH-1 J_USB.NPTH-2 U_LDO.4 U_MAIN.1 U_MAIN.2 U_MAIN.3 U_MAIN.4 U_MAIN.5 U_MAIN.6 U_MAIN.7 U_MAIN.8 U_MAIN.9 U_MAIN.10 U_MAIN.11 U_MAIN.14 U_MAIN.15 U_MAIN.16 U_MAIN.17 U_MAIN.18 U_MAIN.19 U_MAIN.20 U_MAIN.21 U_MAIN.22 U_MAIN.23 U_MAIN.24 U_MAIN.25 U_MAIN.26 U_MAIN.27 U_MAIN.28 U_MAIN.33 U_MAIN.34 U_MAIN.35 U_MAIN.36 U_MAIN.37 U_MAIN.39 U_MAIN.43 U_MAIN.44 U_MAIN.45 U_MAIN.46 U_MAIN.47 U_MAIN.48 U_MAIN.49 U_MAIN.54 U_MAIN.55 U_MAIN.56 U_MAIN.57 U_MAIN.62 U_MAIN.63 U_MAIN.64

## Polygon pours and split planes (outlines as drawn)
GND on Bottom (solid): 107.1,77.1 25.7,77.1 25.7,25.7 107.1,25.7
GND on Bottom (solid): 64.917,57.515 64.917,57.486 64.949,57.489
GND on Bottom (solid): 64.266,55.878 64.211,55.873 64.105,55.767 64.105,55.678 64.105,54.296 64.121,54.3 64.199,54.308 64.264,54.302
GND on Bottom (solid): 62.797,59.612 62.797,58.975 62.792,58.925 62.778,58.876 62.754,58.831 62.721,58.792 59.576,55.646 59.579,55.617 59.571,55.539 59.549,55.464 59.512,55.395 59.462,55.334 59.401,55.284 59.332,55.247 59.257,55.225 59.179,55.217 59.101,55.225 59.026,55.247 58.957,55.284 58.93,55.307 58.93,53.801 60.468,55.376 60.469,55.376 60.471,55.379 60.49,55.395 60.489,55.395 60.702,55.571 60.703,55.57 60.723,55.586 60.768,55.61 60.817,55.625 60.867,55.63 61.101,55.63 63.785,58.314 63.781,58.352 63.789,58.43 63.812,58.505 63.849,58.574 63.898,58.635 63.95,58.678 63.017,59.593 62.94,59.585 62.862,59.593
GND on Bottom (solid): 64.268,57.963 64.259,57.96 64.181,57.952 64.16,57.954 61.396,55.19 61.418,55.12 61.42,55.1 61.963,54.557 61.994,54.519 61.995,54.52 62.162,54.293 62.161,54.292 62.17,54.281 62.2,54.224 62.219,54.163 62.225,54.1 62.225,51.7 62.219,51.637 62.2,51.576 62.17,51.519 62.13,51.47 62.081,51.43 62.046,51.411 62.046,51.41 61.766,51.269 61.756,50.147 61.757,50.145 63.585,51.973 63.585,55.678 63.585,55.875 63.59,55.926 63.605,55.975 63.629,56.019 63.661,56.059 63.808,56.206 63.801,56.272 63.809,56.35 63.832,56.425 63.869,56.494 63.918,56.555 63.979,56.605 64.048,56.642 64.123,56.664 64.201,56.672 64.267,56.666
GND on Bottom (solid): 61.15,48.31 61.129,48.289 61.13,48.017 61.144,48.042 61.166,48.069 61.145,48.138 61.138,48.216 61.145,48.294
GND on Bottom (solid): 60.942,40.328 60.415,40.328 58.958,38.877 59.495,38.877

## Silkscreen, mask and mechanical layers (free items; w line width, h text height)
Top Overlay:
  text "2L • BOTTOM GND POUR" at 48.4,75.4 h0.48
  text "ER-CON14HB-1 • 4-WIRE SPI" at 84.4,75.4 h0.55
  text "ER-TFT020-3" at 81.4,28.9 h0.58
  text "QUICK CONFIGURE • SCREEN" at 66.4,27.4 h0.72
